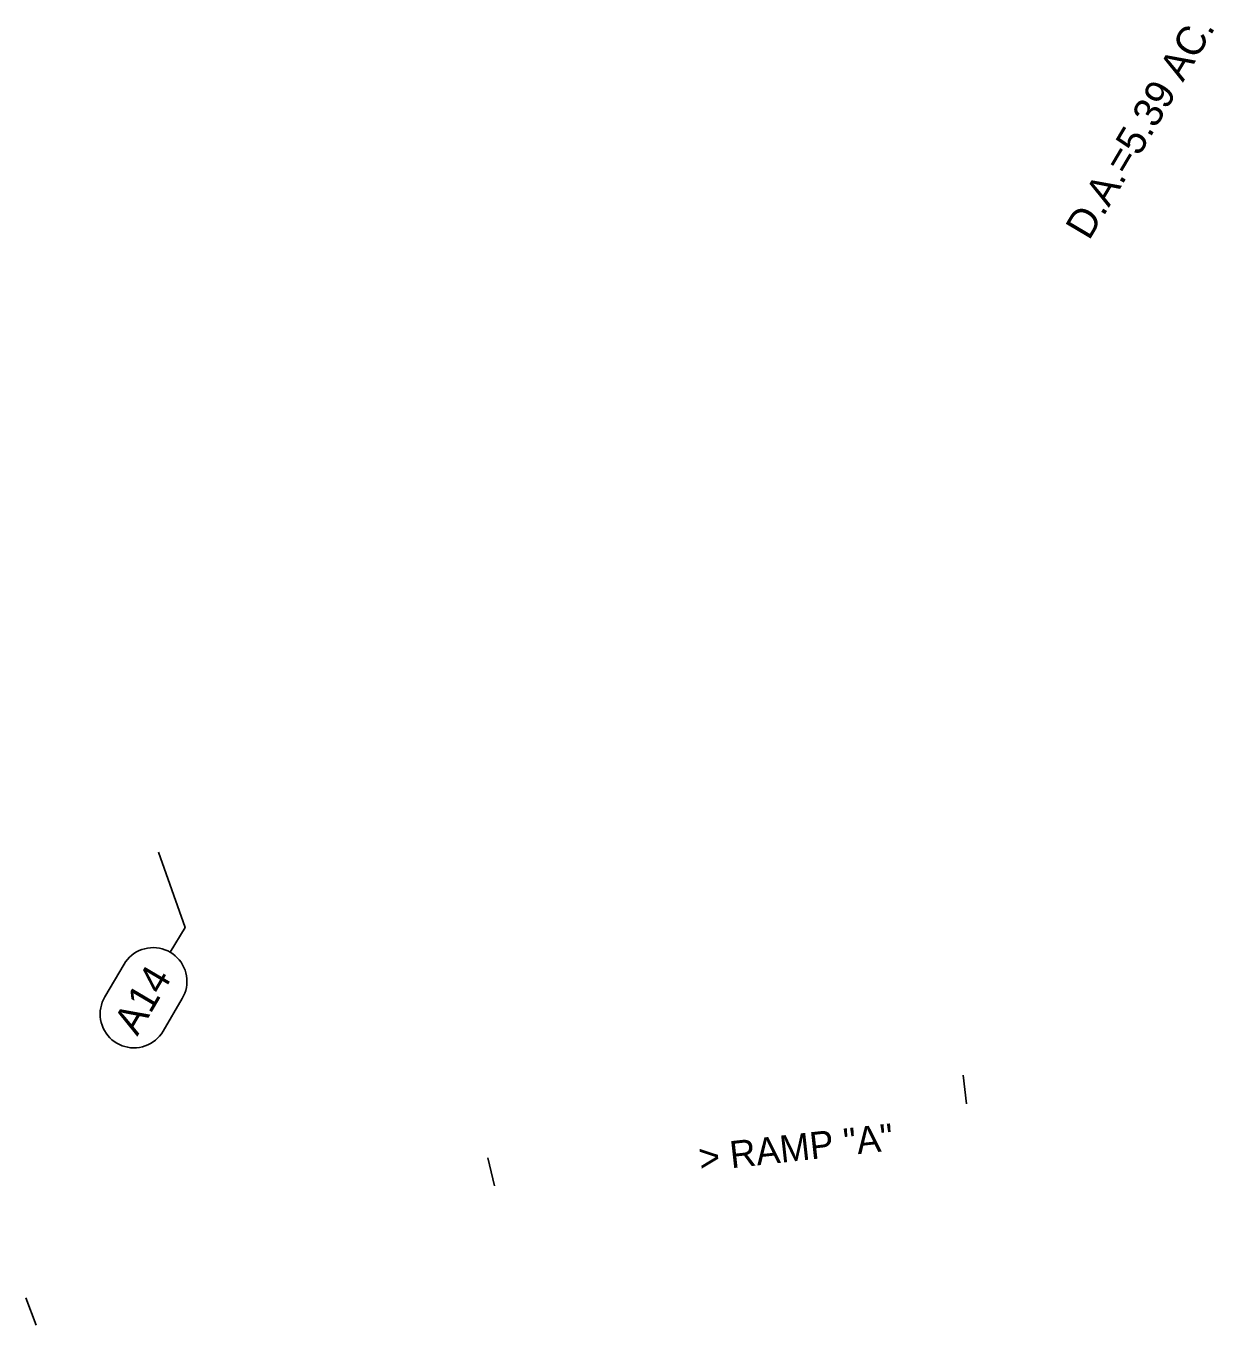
# Model space of a CAD drawing. Extents: x 2149833 to 2151401, y 143015 to 145036.
# Drawn here: x 2150356.6 to 2150602.7, y 143512.2 to 143781.1 of the extents above; entities that cross this region are included whole.
import ezdxf

# ---------------------------------------------------------------- set-up
doc = ezdxf.new("R2010")
doc.units = 0
for name, color, linetype in [('PR_Align_Ramp_A', 7, 'Continuous'), ('PR_Align_Ramp_A_Label', 7, 'Continuous'), ('PR_Storm_Drainage_Area_Txt', 7, 'Continuous'), ('PR_Storm_Txt', 7, 'Continuous')]:
    doc.layers.add(name, color=color, linetype=linetype)

msp = doc.modelspace()

# ---------------------------------------------------------------- linework, layer by layer
at = {"layer": 'PR_Align_Ramp_A'}
for points in [[(2150551.4, 143557.94), (2150550.74, 143563.9)], [(2150551.4, 143557.94), (2150550.74, 143563.9)], [(2150453.67, 143540.94), (2150452.28, 143546.77)], [(2150453.67, 143540.94), (2150452.28, 143546.77)], [(2150358.73, 143512.15), (2150356.64, 143517.77)], [(2150358.73, 143512.15), (2150356.64, 143517.77)]]:
    msp.add_lwpolyline(points, dxfattribs=at)
at = {"layer": 'PR_Storm_Txt'}
msp.add_lwpolyline([(2150384.08, 143610.09), (2150389.58, 143594.49), (2150386.53, 143589.32)], dxfattribs=at)
msp.add_lwpolyline([(2150376.95, 143586.85), (2150372.96, 143580.1), (2150372.68, 143579.56), (2150372.44, 143578.99), (2150372.25, 143578.41), (2150372.11, 143577.82), (2150372.03, 143577.21), (2150371.99, 143576.6), (2150372.01, 143575.99), (2150372.09, 143575.39), (2150372.21, 143574.79), (2150372.39, 143574.21), (2150372.62, 143573.64), (2150372.9, 143573.1), (2150373.22, 143572.58), (2150373.59, 143572.09), (2150374, 143571.64), (2150374.44, 143571.22), (2150374.92, 143570.84), (2150375.44, 143570.51), (2150375.44, 143570.51), (2150375.98, 143570.22), (2150376.54, 143569.98), (2150377.12, 143569.8), (2150377.71, 143569.66), (2150378.32, 143569.57), (2150378.93, 143569.54), (2150379.54, 143569.56), (2150380.14, 143569.64), (2150380.74, 143569.76), (2150381.33, 143569.94), (2150381.89, 143570.17), (2150382.44, 143570.45), (2150382.95, 143570.77), (2150383.44, 143571.14), (2150383.9, 143571.54), (2150384.31, 143571.99), (2150384.69, 143572.47), (2150385.02, 143572.98), (2150389.01, 143579.74), (2150389.29, 143580.28), (2150389.53, 143580.84), (2150389.72, 143581.42), (2150389.86, 143582.02), (2150389.94, 143582.62), (2150389.98, 143583.23), (2150389.95, 143583.84), (2150389.88, 143584.45), (2150389.75, 143585.04), (2150389.58, 143585.63), (2150389.35, 143586.19), (2150389.07, 143586.74), (2150388.75, 143587.26), (2150388.38, 143587.74), (2150387.97, 143588.2), (2150387.52, 143588.62), (2150387.04, 143588.99), (2150386.53, 143589.32), (2150386.53, 143589.32), (2150385.99, 143589.61), (2150385.43, 143589.85), (2150384.85, 143590.04), (2150384.26, 143590.18), (2150383.65, 143590.26), (2150383.04, 143590.29), (2150382.43, 143590.27), (2150381.82, 143590.2), (2150381.23, 143590.07), (2150380.64, 143589.89), (2150380.08, 143589.67), (2150379.53, 143589.39), (2150379.01, 143589.07), (2150378.53, 143588.7), (2150378.07, 143588.29), (2150377.66, 143587.84), (2150377.28, 143587.36)], close=True, dxfattribs=at)

# ---------------------------------------------------------------- texts
at = {"layer": 'PR_Align_Ramp_A_Label'}
msp.add_text('> RAMP "A"', height=5.6, rotation=6.3548, dxfattribs=at).set_placement((2150496.28, 143543.88))
at = {"layer": 'PR_Storm_Drainage_Area_Txt'}
msp.add_text('D.A.=5.39 AC.', height=6, rotation=59.3595, dxfattribs=at).set_placement((2150576.79, 143736.55))
at = {"layer": 'PR_Storm_Txt'}
msp.add_text('A14', height=6, rotation=59.4713, dxfattribs=at).set_placement((2150379.69, 143571.82))

doc.saveas('drawing.dxf')
